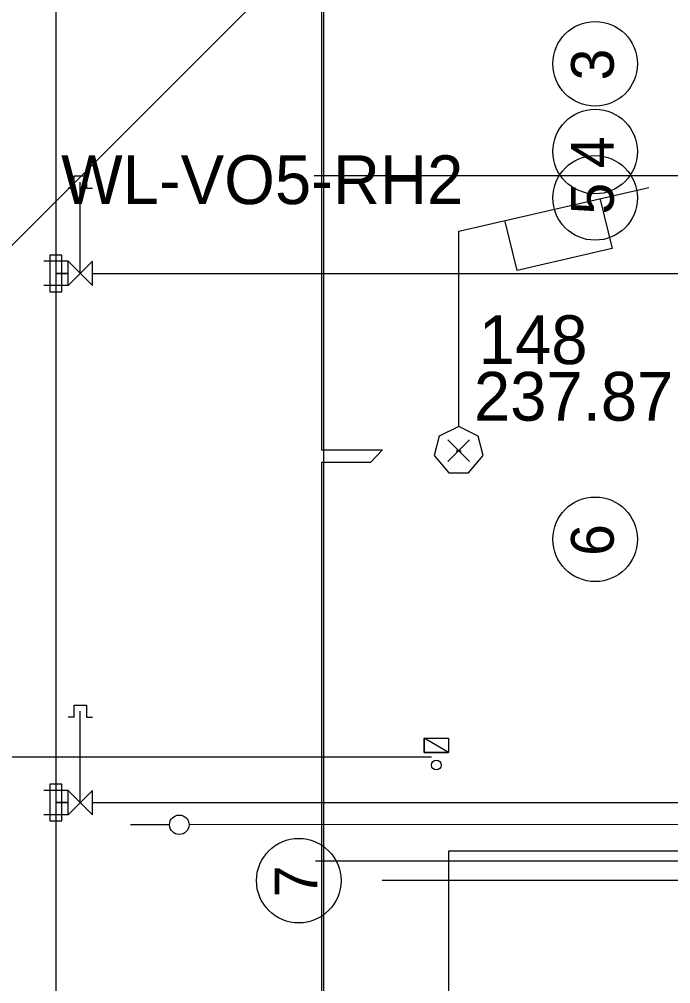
# Model space of a CAD drawing. Extents: x -264222 to -263592, y -1242345 to -1242048.
# Drawn here: x -263924.89 to -263911.54, y -1242121 to -1242101.22 of the extents above; entities that cross this region are included whole.
import ezdxf

# ---------------------------------------------------------------- set-up
doc = ezdxf.new("R2010")
doc.units = 0
for name, color, linetype in [('BOD_CISLO', 7, 'Continuous'), ('BOD_SYMBOL', 7, 'Continuous'), ('BOD_VYSKA', 7, 'Continuous'), ('HESCON_OSI_STAVBY_KFA', 7, 'Continuous'), ('KFA_2D_SITUACIA_DSP', 7, 'Continuous'), ('KFA_SO_62-1_VO_LAMPY_MERANE', 7, 'Continuous'), ('KFA_SO_62-1_VO_POPIS_LAMP_PROJEKT', 7, 'Continuous'), ('KFA_SO_62-1_VO_TRASA_KABLOV_PROJEKT', 7, 'Continuous')]:
    doc.layers.add(name, color=color, linetype=linetype)

msp = doc.modelspace()

# ---------------------------------------------------------------- linework, layer by layer
at = {"layer": 'BOD_SYMBOL'}
for p, q in [((-263916.104, -1242110.289), (-263915.662, -1242109.847)), ((-263915.662, -1242110.289), (-263916.104, -1242109.847))]:
    msp.add_line(p, q, dxfattribs=at)
at = {"layer": 'HESCON_OSI_STAVBY_KFA'}
msp.add_line((-263792.653, -1242118.882), (-263917.453, -1242118.882), dxfattribs=at)
for centre in [(-263913.085, -1242102.133), (-263913.085, -1242103.933), (-263913.085, -1242104.883), (-263913.085, -1242111.883), (-263919.163, -1242118.883)]:
    msp.add_circle(centre, 0.867, dxfattribs=at)
at = {"layer": 'KFA_2D_SITUACIA_DSP'}
for p, q in [((-263924.143, -1242082.64), (-263924.143, -1242185.14)), ((-263916.414, -1242097.223), (-263926.239, -1242107.049)), ((-263923.768, -1242104.682), (-263923.768, -1242104.432)), ((-263923.768, -1242104.432), (-263923.518, -1242104.432)), ((-263923.518, -1242104.432), (-263923.518, -1242104.682)), ((-263908.718, -1242104.427), (-263918.846, -1242104.427)), ((-263923.768, -1242104.682), (-263923.893, -1242104.682)), ((-263923.643, -1242106.432), (-263923.643, -1242104.557)), ((-263923.518, -1242104.682), (-263923.393, -1242104.682)), ((-263924.018, -1242106.057), (-263924.268, -1242106.057)), ((-263924.268, -1242106.057), (-263924.268, -1242106.807)), ((-263924.018, -1242106.807), (-263924.018, -1242106.057)), ((-263923.893, -1242106.182), (-263924.393, -1242106.182)), ((-263923.893, -1242106.682), (-263923.893, -1242106.182)), ((-263923.893, -1242106.182), (-263923.393, -1242106.682)), ((-263923.393, -1242106.182), (-263923.893, -1242106.682)), ((-263923.393, -1242106.682), (-263923.393, -1242106.182)), ((-263924.143, -1242106.432), (-263923.893, -1242106.432)), ((-263923.893, -1242106.432), (-263924.143, -1242106.432)), ((-263923.393, -1242106.432), (-263903.343, -1242106.432)), ((-263923.893, -1242106.682), (-263924.393, -1242106.682)), ((-263924.268, -1242106.807), (-263924.018, -1242106.807)), ((-263923.768, -1242115.532), (-263923.768, -1242115.282)), ((-263923.768, -1242115.282), (-263923.518, -1242115.282)), ((-263923.518, -1242115.282), (-263923.518, -1242115.532)), ((-263923.768, -1242115.532), (-263923.893, -1242115.532)), ((-263923.643, -1242117.282), (-263923.643, -1242115.407)), ((-263923.518, -1242115.532), (-263923.393, -1242115.532)), ((-263916.593, -1242116.252), (-263916.593, -1242115.962)), ((-263916.593, -1242115.962), (-263916.093, -1242115.962)), ((-263916.093, -1242116.252), (-263916.593, -1242115.962)), ((-263916.093, -1242116.252), (-263916.593, -1242115.962)), ((-263916.593, -1242115.962), (-263916.593, -1242116.252)), ((-263916.093, -1242115.962), (-263916.093, -1242116.252)), ((-263916.443, -1242116.352), (-263925.797, -1242116.352)), ((-263916.093, -1242116.252), (-263916.593, -1242116.252)), ((-263916.593, -1242116.252), (-263916.093, -1242116.252)), ((-263924.018, -1242116.907), (-263924.268, -1242116.907)), ((-263924.268, -1242116.907), (-263924.268, -1242117.657)), ((-263924.018, -1242117.657), (-263924.018, -1242116.907)), ((-263923.893, -1242117.032), (-263924.393, -1242117.032)), ((-263923.893, -1242117.532), (-263923.893, -1242117.032)), ((-263923.893, -1242117.032), (-263923.393, -1242117.532)), ((-263923.393, -1242117.032), (-263923.893, -1242117.532)), ((-263923.393, -1242117.532), (-263923.393, -1242117.032)), ((-263924.143, -1242117.282), (-263923.893, -1242117.282)), ((-263923.893, -1242117.282), (-263924.143, -1242117.282)), ((-263923.393, -1242117.282), (-263906.493, -1242117.282)), ((-263923.893, -1242117.532), (-263924.393, -1242117.532)), ((-263924.268, -1242117.657), (-263924.018, -1242117.657)), ((-263921.812, -1242117.737), (-263922.612, -1242117.737)), ((-263903.343, -1242117.732), (-263921.412, -1242117.737)), ((-263908.718, -1242118.482), (-263918.819, -1242118.482))]:
    msp.add_line(p, q, dxfattribs=at)
msp.add_lwpolyline([(-263893.618, -1242118.282), (-263916.093, -1242118.282), (-263916.093, -1242175.482), (-263914.293, -1242175.482), (-263914.293, -1242210.482), (-263893.618, -1242210.482), (-263893.618, -1242166.382), (-263900.043, -1242166.382), (-263900.043, -1242162.382), (-263893.618, -1242162.382)], close=True, dxfattribs=at)
for centre, radius in [((-263916.343, -1242116.514), 0.1), ((-263921.612, -1242117.737), 0.2)]:
    msp.add_circle(centre, radius, dxfattribs=at)
at = {"layer": 'KFA_SO_62-1_VO_LAMPY_MERANE'}
for p, q in [((-263915.933, -1242110.068), (-263915.833, -1242110.068)), ((-263915.883, -1242110.068), (-263915.883, -1242110.068))]:
    msp.add_line(p, q, dxfattribs=at)
for points in [[(-263915.883, -1242109.568), (-263916.283, -1242109.768), (-263916.383, -1242110.168), (-263916.083, -1242110.518), (-263915.683, -1242110.518), (-263915.383, -1242110.168), (-263915.483, -1242109.768), (-263915.883, -1242109.568), (-263915.883, -1242105.568), (-263911.983, -1242104.668)], [(-263912.983, -1242104.918), (-263912.733, -1242105.918), (-263914.683, -1242106.368), (-263914.933, -1242105.368)]]:
    msp.add_lwpolyline(points, dxfattribs=at)
at = {"layer": 'KFA_SO_62-1_VO_TRASA_KABLOV_PROJEKT'}
for p, q in [((-263918.645, -1242194.9), (-263918.645, -1242084.831)), ((-263918.693, -1242090.852), (-263918.693, -1242110.05)), ((-263918.693, -1242110.05), (-263917.446, -1242110.05)), ((-263917.446, -1242110.05), (-263917.689, -1242110.308)), ((-263917.689, -1242110.308), (-263918.695, -1242110.308)), ((-263918.695, -1242110.308), (-263918.695, -1242194.95))]:
    msp.add_line(p, q, dxfattribs=at)

# ---------------------------------------------------------------- texts
at = {"layer": 'BOD_CISLO'}
msp.add_text('148', height=1, dxfattribs=at).set_placement((-263915.472, -1242108.291))
at = {"layer": 'BOD_VYSKA'}
msp.add_text('237.87', height=1, dxfattribs=at).set_placement((-263915.571, -1242109.451))
at = {"layer": 'HESCON_OSI_STAVBY_KFA'}
for s, p in [('3', (-263912.704, -1242102.473)), ('4', (-263912.704, -1242104.273)), ('5', (-263912.704, -1242105.223)), ('6', (-263912.704, -1242112.223)), ('7', (-263918.782, -1242119.223))]:
    msp.add_text(s, height=0.875, rotation=90, dxfattribs=at).set_placement(p)
at = {"layer": 'KFA_SO_62-1_VO_POPIS_LAMP_PROJEKT'}
msp.add_text('WL-VO5-RH2', height=1, dxfattribs=at).set_placement((-263924.035, -1242105.01))

doc.saveas('drawing.dxf')
